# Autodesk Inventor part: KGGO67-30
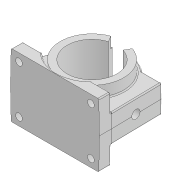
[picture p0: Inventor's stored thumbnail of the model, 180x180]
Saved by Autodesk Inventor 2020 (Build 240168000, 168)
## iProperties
Created: 2020-03
Part Number: KGGO67-30
Material: Všeobecné
Description: STEP AP203
Document SubType Name: Modeling
Designer: Marek Nesvadba
Density: 1 g/cm^3
Appearance: Výchozí
Title: KGGO67-30.step
Revision Number: ANY
Sending System: SolidWorks 2019
Preprocessor: SwSTEP 2.0
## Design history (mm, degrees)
feature "_KBLS-30_Gussteil_-_Verrundung15_"
node "Těleso1"
